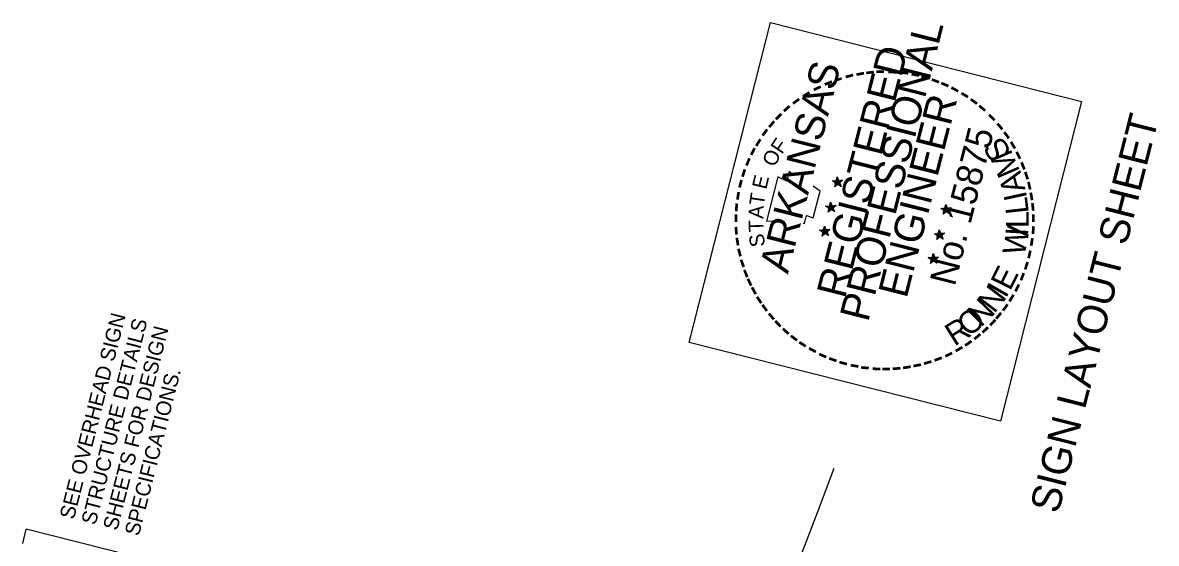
# Model space of a CAD drawing. Extents: x 670006 to 670131, y 737844 to 738002.
# Drawn here: x 670082.89 to 670130.78, y 737962 to 737984.02 of the extents above; entities that cross this region are included whole.
import ezdxf

# ---------------------------------------------------------------- set-up
doc = ezdxf.new("R2010")
doc.units = 0
for name, color, linetype in [('R_Border Notes', 7, 'Continuous'), ('R_Border PE', 7, 'Continuous'), ('R_Border Prem', 7, 'Continuous'), ('R_Exist Surface', 7, 'Continuous'), ('R_SIGN', 7, 'Continuous'), ('R_SIGN_ANNOT', 7, 'Continuous')]:
    doc.layers.add(name, color=color, linetype=linetype)

msp = doc.modelspace()

# ---------------------------------------------------------------- linework, layer by layer
at = {"layer": 'R_Border PE'}
for p, q in [((670117.092, 737977.331), (670117.254, 737977.335)), ((670117.31, 737977.275), (670117.092, 737977.331)), ((670117.092, 737977.331), (670117.251, 737977.323)), ((670117.092, 737977.331), (670117.24, 737977.306)), ((670117.092, 737977.331), (670117.24, 737977.28)), ((670117.092, 737977.331), (670117.237, 737977.268)), ((670117.092, 737977.331), (670117.228, 737977.258)), ((670117.297, 737977.504), (670117.262, 737977.314)), ((670117.297, 737977.504), (670117.283, 737977.321)), ((670117.297, 737977.504), (670117.295, 737977.318)), ((670117.297, 737977.504), (670117.31, 737977.275)), ((670117.297, 737977.504), (670117.318, 737977.357)), ((670117.297, 737977.504), (670117.326, 737977.362)), ((670117.297, 737977.504), (670117.335, 737977.372)), ((670117.524, 737977.357), (670117.31, 737977.275)), ((670117.524, 737977.357), (670117.328, 737977.322)), ((670117.524, 737977.357), (670117.331, 737977.335)), ((670117.524, 737977.357), (670117.351, 737977.31)), ((670117.524, 737977.357), (670117.359, 737977.263)), ((670117.524, 737977.357), (670117.371, 737977.286)), ((670117.524, 737977.357), (670117.377, 737977.259)), ((670117.19, 737977.08), (670117.31, 737977.275)), ((670117.19, 737977.08), (670117.248, 737977.233)), ((670117.19, 737977.08), (670117.258, 737977.224)), ((670117.19, 737977.08), (670117.264, 737977.223)), ((670117.19, 737977.08), (670117.287, 737977.21)), ((670117.19, 737977.08), (670117.299, 737977.207)), ((670117.19, 737977.08), (670117.311, 737977.204)), ((670117.458, 737977.096), (670117.307, 737977.212)), ((670117.458, 737977.096), (670117.31, 737977.275)), ((670117.458, 737977.096), (670117.327, 737977.213)), ((670117.458, 737977.096), (670117.336, 737977.224)), ((670117.458, 737977.096), (670117.358, 737977.237)), ((670117.458, 737977.096), (670117.359, 737977.263)), ((670117.458, 737977.096), (670117.378, 737977.265)), ((670117.019, 737976.434), (670116.984, 737976.243)), ((670117.019, 737976.434), (670117.005, 737976.25)), ((670117.019, 737976.434), (670117.017, 737976.247)), ((670117.019, 737976.434), (670117.032, 737976.205)), ((670117.019, 737976.434), (670117.04, 737976.287)), ((670117.019, 737976.434), (670117.049, 737976.297)), ((670117.019, 737976.434), (670117.057, 737976.302)), ((670116.808, 737976.262), (670116.976, 737976.264)), ((670117.032, 737976.205), (670116.808, 737976.262)), ((670116.808, 737976.262), (670116.967, 737976.253)), ((670116.808, 737976.262), (670116.962, 737976.235)), ((670116.808, 737976.262), (670116.956, 737976.211)), ((670116.808, 737976.262), (670116.959, 737976.197)), ((670116.808, 737976.262), (670116.952, 737976.193)), ((670116.912, 737976.01), (670117.032, 737976.205)), ((670116.912, 737976.01), (670116.964, 737976.164)), ((670116.912, 737976.01), (670116.976, 737976.161)), ((670116.912, 737976.01), (670116.986, 737976.152)), ((670116.912, 737976.01), (670117.009, 737976.14)), ((670116.912, 737976.01), (670117.021, 737976.137)), ((670116.912, 737976.01), (670117.033, 737976.133)), ((670117.182, 737976.031), (670117.029, 737976.141)), ((670117.248, 737976.292), (670117.032, 737976.205)), ((670117.182, 737976.031), (670117.032, 737976.205)), ((670117.248, 737976.292), (670117.047, 737976.265)), ((670117.182, 737976.031), (670117.049, 737976.142)), ((670117.248, 737976.292), (670117.05, 737976.252)), ((670117.182, 737976.031), (670117.058, 737976.153)), ((670117.248, 737976.292), (670117.073, 737976.239)), ((670117.182, 737976.031), (670117.08, 737976.167)), ((670117.248, 737976.292), (670117.081, 737976.192)), ((670117.182, 737976.031), (670117.081, 737976.192)), ((670117.248, 737976.292), (670117.093, 737976.215)), ((670117.248, 737976.292), (670117.099, 737976.188)), ((670117.182, 737976.031), (670117.1, 737976.194)), ((670121.896, 737976.112), (670121.678, 737976.168)), ((670121.678, 737976.168), (670121.839, 737976.166)), ((670121.678, 737976.168), (670121.837, 737976.16)), ((670121.678, 737976.168), (670121.833, 737976.141)), ((670121.678, 737976.168), (670121.826, 737976.117)), ((670121.678, 737976.168), (670121.823, 737976.105)), ((670121.678, 737976.168), (670121.82, 737976.093)), ((670121.776, 737975.917), (670121.896, 737976.112)), ((670121.776, 737975.917), (670121.832, 737976.064)), ((670121.776, 737975.917), (670121.844, 737976.061)), ((670121.776, 737975.917), (670121.855, 737976.052)), ((670121.776, 737975.917), (670121.873, 737976.047)), ((670121.776, 737975.917), (670121.89, 737976.037)), ((670121.776, 737975.917), (670121.902, 737976.033)), ((670121.882, 737976.335), (670121.848, 737976.15)), ((670121.882, 737976.335), (670121.869, 737976.158)), ((670121.882, 737976.335), (670121.881, 737976.155)), ((670121.882, 737976.335), (670121.896, 737976.112)), ((670121.882, 737976.335), (670121.902, 737976.188)), ((670121.882, 737976.335), (670121.918, 737976.197)), ((670121.882, 737976.335), (670121.925, 737976.202)), ((670122.044, 737975.933), (670121.891, 737976.043)), ((670122.11, 737976.193), (670121.896, 737976.112)), ((670122.044, 737975.933), (670121.896, 737976.112)), ((670122.11, 737976.193), (670121.913, 737976.153)), ((670122.11, 737976.193), (670121.916, 737976.165)), ((670122.044, 737975.933), (670121.917, 737976.043)), ((670122.044, 737975.933), (670121.928, 737976.059)), ((670122.11, 737976.193), (670121.942, 737976.139)), ((670122.044, 737975.933), (670121.945, 737976.074)), ((670122.11, 737976.193), (670121.949, 737976.092)), ((670122.044, 737975.933), (670121.949, 737976.092)), ((670122.11, 737976.193), (670121.955, 737976.117)), ((670122.044, 737975.933), (670121.963, 737976.095)), ((670122.11, 737976.193), (670121.967, 737976.088)), ((670116.763, 737975.422), (670116.727, 737975.231)), ((670116.763, 737975.422), (670116.748, 737975.239)), ((670116.763, 737975.422), (670116.76, 737975.235)), ((670116.763, 737975.422), (670116.775, 737975.193)), ((670116.763, 737975.422), (670116.783, 737975.275)), ((670116.763, 737975.422), (670116.792, 737975.285)), ((670116.763, 737975.422), (670116.8, 737975.29)), ((670116.551, 737975.25), (670116.72, 737975.252)), ((670116.775, 737975.193), (670116.551, 737975.25)), ((670116.551, 737975.25), (670116.71, 737975.242)), ((670116.551, 737975.25), (670116.707, 737975.23)), ((670116.551, 737975.25), (670116.701, 737975.205)), ((670116.551, 737975.25), (670116.703, 737975.186)), ((670116.551, 737975.25), (670116.695, 737975.181)), ((670116.655, 737974.998), (670116.775, 737975.193)), ((670116.655, 737974.998), (670116.707, 737975.152)), ((670116.655, 737974.998), (670116.719, 737975.149)), ((670116.655, 737974.998), (670116.73, 737975.14)), ((670116.655, 737974.998), (670116.754, 737975.134)), ((670116.655, 737974.998), (670116.765, 737975.125)), ((670116.655, 737974.998), (670116.777, 737975.122)), ((670116.925, 737975.02), (670116.772, 737975.129)), ((670116.991, 737975.28), (670116.775, 737975.193)), ((670116.925, 737975.02), (670116.775, 737975.193)), ((670116.991, 737975.28), (670116.791, 737975.254)), ((670116.925, 737975.02), (670116.792, 737975.131)), ((670116.991, 737975.28), (670116.794, 737975.24)), ((670116.925, 737975.02), (670116.801, 737975.141)), ((670116.991, 737975.28), (670116.817, 737975.228)), ((670116.991, 737975.28), (670116.824, 737975.181)), ((670116.925, 737975.02), (670116.824, 737975.181)), ((670116.925, 737975.02), (670116.824, 737975.155)), ((670116.991, 737975.28), (670116.836, 737975.203)), ((670116.991, 737975.28), (670116.842, 737975.176)), ((670116.925, 737975.02), (670116.844, 737975.182)), ((670121.618, 737975.042), (670121.4, 737975.097)), ((670121.4, 737975.097), (670121.561, 737975.095)), ((670121.4, 737975.097), (670121.559, 737975.089)), ((670121.4, 737975.097), (670121.555, 737975.071)), ((670121.4, 737975.097), (670121.548, 737975.046)), ((670121.4, 737975.097), (670121.545, 737975.034)), ((670121.4, 737975.097), (670121.536, 737975.024)), ((670121.498, 737974.846), (670121.618, 737975.042)), ((670121.498, 737974.846), (670121.554, 737974.993)), ((670121.498, 737974.846), (670121.566, 737974.99)), ((670121.498, 737974.846), (670121.572, 737974.989)), ((670121.498, 737974.846), (670121.595, 737974.976)), ((670121.498, 737974.846), (670121.607, 737974.973)), ((670121.498, 737974.846), (670121.619, 737974.97)), ((670121.604, 737975.264), (670121.57, 737975.08)), ((670121.604, 737975.264), (670121.591, 737975.087)), ((670121.604, 737975.264), (670121.603, 737975.084)), ((670121.604, 737975.264), (670121.618, 737975.042)), ((670121.604, 737975.264), (670121.624, 737975.117)), ((670121.604, 737975.264), (670121.634, 737975.128)), ((670121.604, 737975.264), (670121.649, 737975.137)), ((670121.766, 737974.862), (670121.615, 737974.978)), ((670121.832, 737975.123), (670121.618, 737975.042)), ((670121.766, 737974.862), (670121.618, 737975.042)), ((670121.832, 737975.123), (670121.635, 737975.082)), ((670121.832, 737975.123), (670121.64, 737975.101)), ((670121.766, 737974.862), (670121.641, 737974.978)), ((670121.766, 737974.862), (670121.65, 737974.988)), ((670121.832, 737975.123), (670121.659, 737975.076)), ((670121.766, 737974.862), (670121.666, 737975.004)), ((670121.766, 737974.862), (670121.667, 737975.029)), ((670121.832, 737975.123), (670121.673, 737975.028)), ((670121.832, 737975.123), (670121.677, 737975.046)), ((670121.832, 737975.123), (670121.683, 737975.019)), ((670121.766, 737974.862), (670121.685, 737975.025)), ((670121.143, 737974.085), (670121.306, 737974.089)), ((670121.362, 737974.03), (670121.143, 737974.085)), ((670121.143, 737974.085), (670121.303, 737974.077)), ((670121.143, 737974.085), (670121.298, 737974.059)), ((670121.143, 737974.085), (670121.292, 737974.035)), ((670121.143, 737974.085), (670121.289, 737974.023)), ((670121.143, 737974.085), (670121.28, 737974.012)), ((670121.241, 737973.835), (670121.362, 737974.03)), ((670121.241, 737973.835), (670121.299, 737973.988)), ((670121.241, 737973.835), (670121.31, 737973.978)), ((670121.241, 737973.835), (670121.316, 737973.977)), ((670121.349, 737974.259), (670121.313, 737974.068)), ((670121.349, 737974.259), (670121.334, 737974.075)), ((670121.349, 737974.259), (670121.346, 737974.072)), ((670121.349, 737974.259), (670121.362, 737974.03)), ((670121.349, 737974.259), (670121.368, 737974.106)), ((670121.349, 737974.259), (670121.377, 737974.116)), ((670121.349, 737974.259), (670121.392, 737974.125)), ((670121.576, 737974.111), (670121.362, 737974.03)), ((670121.509, 737973.85), (670121.362, 737974.03)), ((670121.576, 737974.111), (670121.378, 737974.071)), ((670121.576, 737974.111), (670121.383, 737974.089)), ((670121.509, 737973.85), (670121.393, 737973.977)), ((670121.576, 737974.111), (670121.403, 737974.065)), ((670121.509, 737973.85), (670121.41, 737974.018)), ((670121.509, 737973.85), (670121.41, 737973.992)), ((670121.576, 737974.111), (670121.416, 737974.016)), ((670121.576, 737974.111), (670121.421, 737974.034)), ((670121.576, 737974.111), (670121.427, 737974.007)), ((670121.509, 737973.85), (670121.428, 737974.013)), ((670121.241, 737973.835), (670121.339, 737973.965)), ((670121.241, 737973.835), (670121.351, 737973.962)), ((670121.241, 737973.835), (670121.363, 737973.959)), ((670121.509, 737973.85), (670121.358, 737973.966)), ((670121.509, 737973.85), (670121.384, 737973.966))]:
    msp.add_line(p, q, dxfattribs=at)
for points in [[(670115.409, 737977.609), (670115.261, 737977.737), (670115.167, 737977.316), (670114.79, 737977.508), (670114.312, 737975.624)], [(670117.092, 737977.331), (670117.524, 737977.357), (670117.19, 737977.08), (670117.297, 737977.504), (670117.458, 737977.096), (670117.092, 737977.331)], [(670115.854, 737975.549), (670115.908, 737975.535), (670116.006, 737975.872), (670116.283, 737975.769), (670116.571, 737976.902), (670116.28, 737977.105)], [(670116.808, 737976.262), (670117.248, 737976.292), (670116.912, 737976.01), (670117.019, 737976.434), (670117.182, 737976.031), (670116.808, 737976.262)], [(670121.678, 737976.168), (670122.11, 737976.193), (670121.776, 737975.917), (670121.882, 737976.335), (670122.044, 737975.933), (670121.678, 737976.168)], [(670114.312, 737975.624), (670114.855, 737975.654)], [(670116.551, 737975.25), (670116.991, 737975.28), (670116.655, 737974.998), (670116.763, 737975.422), (670116.925, 737975.02), (670116.551, 737975.25)], [(670121.4, 737975.097), (670121.832, 737975.123), (670121.498, 737974.846), (670121.604, 737975.264), (670121.766, 737974.862), (670121.4, 737975.097)], [(670121.143, 737974.085), (670121.576, 737974.111), (670121.241, 737973.835), (670121.349, 737974.259), (670121.509, 737973.85), (670121.143, 737974.085)]]:
    msp.add_lwpolyline(points, dxfattribs=at)
for centre, radius in [((670117.311, 737977.275), 0.108), ((670117.311, 737977.275), 0.0975), ((670117.311, 737977.275), 0.0904), ((670117.311, 737977.275), 0.083), ((670117.311, 737977.275), 0.0723), ((670117.311, 737977.275), 0.0672), ((670117.311, 737977.275), 0.0619), ((670117.311, 737977.275), 0.0533), ((670117.311, 737977.275), 0.0467), ((670117.311, 737977.275), 0.0388), ((670117.311, 737977.275), 0.031), ((670117.311, 737977.275), 0.0231), ((670117.311, 737977.275), 0.0185), ((670117.311, 737977.275), 0.00901), ((670117.033, 737976.206), 0.108), ((670117.033, 737976.206), 0.0975), ((670117.033, 737976.206), 0.0904), ((670117.033, 737976.206), 0.083), ((670117.033, 737976.206), 0.0723), ((670117.033, 737976.206), 0.0672), ((670117.033, 737976.206), 0.0619), ((670117.033, 737976.206), 0.0533), ((670117.033, 737976.206), 0.0467), ((670117.033, 737976.206), 0.0388), ((670117.033, 737976.206), 0.031), ((670117.033, 737976.206), 0.0231), ((670117.033, 737976.206), 0.0185), ((670117.033, 737976.206), 0.00901), ((670121.899, 737976.109), 0.108), ((670121.899, 737976.109), 0.0975), ((670121.899, 737976.109), 0.0904), ((670121.899, 737976.109), 0.083), ((670121.899, 737976.109), 0.0723), ((670121.899, 737976.109), 0.0672), ((670121.899, 737976.109), 0.0619), ((670121.899, 737976.109), 0.0533), ((670121.899, 737976.109), 0.0467), ((670121.899, 737976.109), 0.0388), ((670121.899, 737976.109), 0.031), ((670121.899, 737976.109), 0.0231), ((670121.899, 737976.109), 0.0185), ((670121.899, 737976.109), 0.00901), ((670116.776, 737975.195), 0.108), ((670116.776, 737975.195), 0.0975), ((670116.776, 737975.195), 0.0904), ((670116.776, 737975.195), 0.083), ((670116.776, 737975.195), 0.0723), ((670116.776, 737975.195), 0.0672), ((670116.776, 737975.195), 0.0619), ((670116.776, 737975.195), 0.0533), ((670116.776, 737975.195), 0.0467), ((670116.776, 737975.195), 0.0388), ((670116.776, 737975.195), 0.031), ((670116.776, 737975.195), 0.0231), ((670116.776, 737975.195), 0.0185), ((670116.776, 737975.195), 0.00901), ((670121.62, 737975.04), 0.108), ((670121.62, 737975.04), 0.0975), ((670121.62, 737975.04), 0.0904), ((670121.62, 737975.04), 0.083), ((670121.62, 737975.04), 0.0723), ((670121.62, 737975.04), 0.0672), ((670121.62, 737975.04), 0.0619), ((670121.62, 737975.04), 0.0533), ((670121.62, 737975.04), 0.0467), ((670121.62, 737975.04), 0.0388), ((670121.62, 737975.04), 0.031), ((670121.62, 737975.04), 0.0231), ((670121.62, 737975.04), 0.0185), ((670121.62, 737975.04), 0.00901), ((670121.364, 737974.029), 0.108), ((670121.364, 737974.029), 0.0975), ((670121.364, 737974.029), 0.0904), ((670121.364, 737974.029), 0.083), ((670121.364, 737974.029), 0.0723), ((670121.364, 737974.029), 0.0672), ((670121.364, 737974.029), 0.0619), ((670121.364, 737974.029), 0.0533), ((670121.364, 737974.029), 0.0467), ((670121.364, 737974.029), 0.0388), ((670121.364, 737974.029), 0.031), ((670121.364, 737974.029), 0.0231), ((670121.364, 737974.029), 0.0185), ((670121.364, 737974.029), 0.00901)]:
    msp.add_circle(centre, radius, dxfattribs=at)
at = {"layer": 'R_Border Prem'}
msp.add_lwpolyline([(670111.048, 737970.5), (670114.477, 737984.022), (670127.623, 737980.688), (670124.194, 737967.166)], close=True, dxfattribs=at)
at = {"layer": 'R_Exist Surface'}
msp.add_lwpolyline([(670114.748, 737958.822), (670116.463, 737963.305), (670117.167, 737965.182)], dxfattribs=at)
at = {"layer": 'R_SIGN'}
for p in [(670082.888, 737962.002), (670111.79, 737955.317)]:
    msp.add_line(p, (670083.041, 737962.608), dxfattribs=at)

# ---------------------------------------------------------------- texts
at = {"layer": 'R_Border Notes'}
msp.add_text('SIGN LAYOUT SHEET', height=1.25, rotation=75.7686, dxfattribs=at).set_placement((670126.637, 737963.215))
at = {"layer": 'R_Border PE'}
for s, height, rotation, p in [('PROFESSIONAL', 1.24999, 75.7686, (670118.6, 737971.326)), ('REGISTERED', 1.25, 75.7686, (670117.625, 737972.315)), ('ARKANSAS', 1.25, 75.7686, (670115.215, 737973.364)), ('-', 0.875, 19.4438, (670117.283, 737981.235)), ('-', 1, 15.4369, (670117.701, 737981.335)), ('-', 1, 10.4313, (670118.12, 737981.435)), ('-', 1, 6.3414, (670118.505, 737981.505)), ('-', 1, 0.8918, (670118.892, 737981.555)), ('-', 1, 356.3179, (670119.377, 737981.561)), ('-', 1, 352.3647, (670119.864, 737981.548)), ('-', 1, 350.0987, (670120.315, 737981.472)), ('-', 1, 345.7092, (670120.701, 737981.393)), ('-', 1, 339.2857, (670121.098, 737981.28)), ('-', 1, 25.6483, (670116.419, 737980.803)), ('-', 1, 22.4207, (670116.862, 737981.026)), ('-', 1, 336.7638, (670121.487, 737981.136)), ('-', 1, 331.5312, (670121.882, 737980.965)), ('-', 1, 36.2983, (670115.609, 737980.254)), ('-', 1, 31.3471, (670115.998, 737980.542)), ('ENGINEER', 1.25, 75.7686, (670120.226, 737972.325)), ('-', 1, 328.6366, (670122.291, 737980.745)), ('-', 1, 323.6572, (670122.663, 737980.509)), ('-', 1, 45.4094, (670114.938, 737979.618)), ('-', 1, 41.6312, (670115.255, 737979.95)), ('-', 1, 320.3883, (670123.003, 737980.248)), ('-', 1, 49.8896, (670114.679, 737979.31)), ('-', 1, 314.8398, (670123.398, 737979.897)), ('-', 1, 309.6138, (670123.73, 737979.555)), ('-', 1, 53.6236, (670114.419, 737978.969)), ('No. 15875', 1.1, 75.7686, (670122.259, 737972.84)), ('-', 1, 307.0223, (670124.009, 737979.207)), ('-', 1, 58.1047, (670114.172, 737978.555)), ('F', 0.625, 55.8392, (670114.958, 737978.426)), ('S', 0.962, 121.462, (670124.682, 737978.528)), ('-', 1, 301.5339, (670124.275, 737978.83)), ('-', 1, 67.9303, (670113.801, 737977.779)), ('-', 1, 62.9734, (670113.978, 737978.198)), ('O', 0.625, 66.2201, (670114.673, 737977.886)), ('M', 0.962, 113.3256, (670125.034, 737977.738)), ('-', 1, 296.8536, (670124.504, 737978.436)), ('-', 1, 73.5116, (670113.651, 737977.339)), ('-', 1, 291.5049, (670124.704, 737978.031)), ('-', 1, 75.9548, (670113.533, 737976.899)), ('E', 0.625, 76.6009, (670114.298, 737976.943)), ('A', 0.962, 105.7601, (670125.258, 737976.966)), ('-', 1, 288.0176, (670124.857, 737977.644)), ('-', 1, 81.6654, (670113.457, 737976.422)), ('-', 1, 283.1254, (670124.985, 737977.257)), ('-', 1, 85.9879, (670113.411, 737975.962)), ('T', 0.625, 81.7913, (670114.196, 737976.26)), ('I', 0.962, 102.3343, (670125.326, 737976.608)), ('L', 0.962, 96.339, (670125.392, 737975.974)), ('-', 1, 280.0202, (670125.082, 737976.826)), ('-', 1, 276.487, (670125.15, 737976.409)), ('-', 1, 89.3987, (670113.404, 737975.526)), ('A', 0.625, 86.9817, (670114.168, 737975.719)), ('L', 0.962, 90.3438, (670125.392, 737975.337)), ('-', 1, 271.2428, (670125.193, 737975.966)), ('T', 0.625, 92.1721, (670114.192, 737975.178)), ('W', 0.962, 78.7816, (670125.205, 737974.124)), ('-', 1, 267.0543, (670125.202, 737975.493)), ('-', 1, 94.9446, (670113.434, 737975.035)), ('S', 0.625, 97.3626, (670114.252, 737974.576)), ('I', 0.962, 86.9179, (670125.362, 737974.974)), ('-', 1, 100.0758, (670113.501, 737974.611)), ('-', 1, 104.5604, (670113.598, 737974.181)), ('-', 1, 261.5852, (670125.167, 737975.025)), ('-', 1, 109.8321, (670113.73, 737973.76)), ('-', 1, 257.3603, (670125.091, 737974.522)), ('-', 1, 112.0003, (670113.877, 737973.349)), ('E', 0.962, 63.7221, (670124.604, 737972.644)), ('-', 1, 252.2868, (670124.989, 737974.071)), ('-', 1, 114.7192, (670114.035, 737973.006)), ('-', 1, 248.884, (670124.838, 737973.625)), ('-', 1, 118.7308, (670114.222, 737972.675)), ('N', 0.962, 52.7308, (670123.932, 737971.689)), ('I', 0.962, 60.2962, (670124.414, 737972.333)), ('-', 1, 238.5668, (670124.445, 737972.764)), ('-', 1, 243.3241, (670124.653, 737973.176)), ('-', 1, 124.1916, (670114.443, 737972.328)), ('-', 1, 126.3827, (670114.673, 737972.012)), ('N', 0.962, 45.1654, (670123.37, 737971.115)), ('-', 1, 234.3298, (670124.213, 737972.385)), ('-', 1, 130.001, (670114.955, 737971.676)), ('O', 0.962, 38.8847, (670122.848, 737970.698)), ('-', 1, 230.3687, (670123.959, 737972.043)), ('-', 1, 133.8392, (670115.225, 737971.395)), ('-', 1, 138.6399, (670115.547, 737971.113)), ('R', 0.962, 32.1757, (670122.245, 737970.318)), ('-', 1, 223.8583, (670123.445, 737971.464)), ('-', 1, 227.3389, (670123.734, 737971.765)), ('-', 1, 143.5428, (670115.877, 737970.862)), ('-', 1, 220.4149, (670123.134, 737971.182)), ('-', 1, 148.163, (670116.225, 737970.632)), ('-', 1, 151.2295, (670116.632, 737970.406)), ('-', 1, 209.9924, (670122.441, 737970.661)), ('-', 1, 214.7024, (670122.8, 737970.905)), ('-', 1, 156.9698, (670117.04, 737970.212)), ('-', 1, 160.9549, (670117.448, 737970.064)), ('-', 1, 164.8308, (670117.867, 737969.938)), ('-', 1, 196.2157, (670121.224, 737970.08)), ('-', 1, 201.662, (670121.624, 737970.236)), ('-', 1, 206.4867, (670122.034, 737970.429)), ('-', 1, 169.9644, (670118.316, 737969.85)), ('-', 1, 174.7165, (670118.726, 737969.791)), ('-', 1, 177.4835, (670119.194, 737969.756)), ('-', 1, 181.2264, (670119.578, 737969.769)), ('-', 1, 184.856, (670119.992, 737969.799)), ('-', 1, 189.8329, (670120.395, 737969.865)), ('-', 1, 191.4974, (670120.817, 737969.951))]:
    msp.add_text(s, height=height, rotation=rotation, dxfattribs=at).set_placement(p)
at = {"layer": 'R_SIGN_ANNOT'}
for s, p in [('SEE OVERHEAD SIGN ', (670085.049, 737962.982)), ('STRUCTURE DETAILS ', (670085.965, 737962.749)), ('SHEETS FOR DESIGN ', (670086.881, 737962.517)), ('SPECIFICATIONS.', (670087.797, 737962.285))]:
    msp.add_text(s, height=0.63, rotation=75.7686, dxfattribs=at).set_placement(p)

doc.saveas('drawing.dxf')
